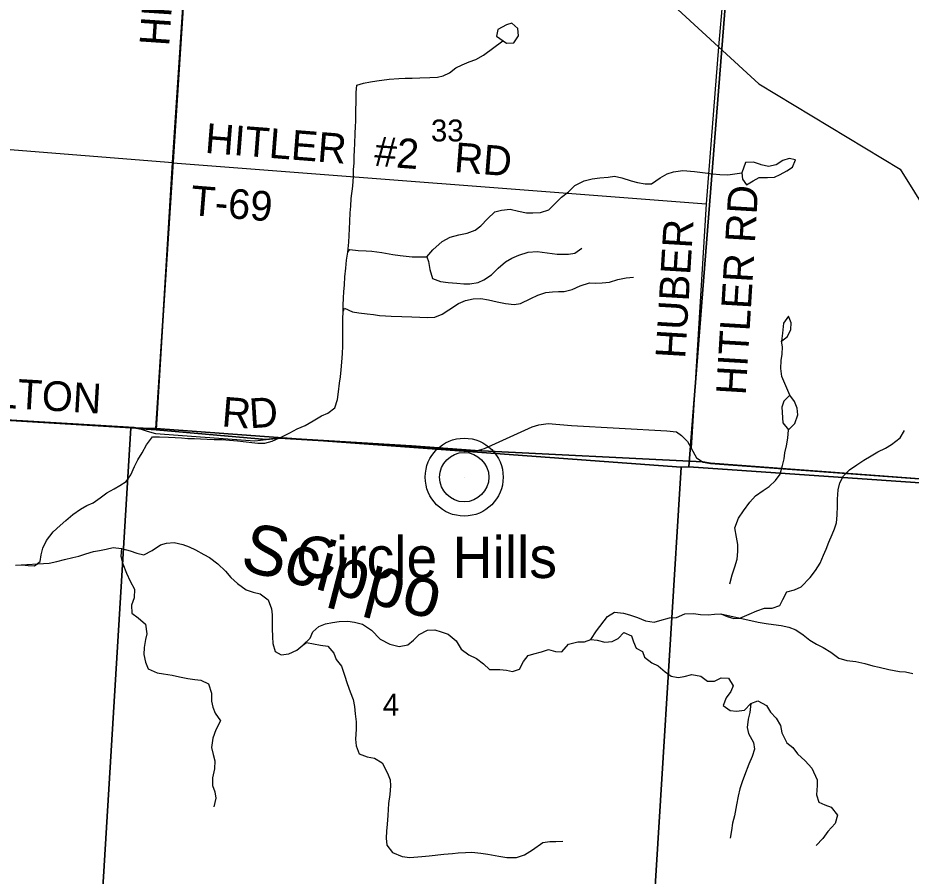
# Model space of a CAD drawing. Extents: x 0 to 42.5, y 0 to 22.
# Drawn here: x 3.26 to 4.113, y 18.558 to 19.377 of the extents above; entities that cross this region are included whole.
import ezdxf

# ---------------------------------------------------------------- set-up
doc = ezdxf.new("R2010")
doc.units = 0
for name, color, linetype in [('GM_X_County_Road', 7, 'Continuous'), ('GM_X_County_Road_Text', 7, 'Continuous'), ('GM_X_Interchange_Ramps', 7, 'Continuous'), ('GM_X_Minor_Lake', 7, 'Continuous'), ('GM_X_Minor_River', 7, 'Continuous'), ('GM_X_Minor_River_Text', 7, 'Continuous'), ('GM_X_Section', 7, 'Continuous'), ('GM_X_Section_Text', 7, 'Continuous'), ('GM_X_State_Route', 7, 'Continuous'), ('GM_X_Township_Road', 7, 'Continuous'), ('GM_X_Township_Road_Text', 7, 'Continuous'), ('GM_X_Unincorporated', 7, 'Continuous'), ('GM_X_Unincorporated_Location', 7, 'Continuous'), ('GM_X_Unincorporated_Text', 7, 'Continuous')]:
    doc.layers.add(name, color=color, linetype=linetype)

msp = doc.modelspace()

# ---------------------------------------------------------------- linework, layer by layer
at = {"layer": 'GM_X_County_Road'}
for points in [[(3.12006, 19.00078), (3.37089, 18.98588), (3.37753, 18.98441), (3.38325, 18.98268)], [(3.70116, 18.96488), (3.70559, 18.96598), (3.75099, 18.98664), (3.75747, 18.98856), (3.76636, 18.98976), (3.78846, 18.98784), (3.87969, 18.98299), (3.88872, 18.98184), (3.89365, 18.97856), (3.8994, 18.9728), (3.90285, 18.96641)], [(3.38325, 18.98268), (3.39135, 18.98024), (3.48609, 18.97319), (3.49698, 18.97445), (3.50982, 18.97594), (3.63593, 18.96814), (3.69673, 18.96377), (3.70116, 18.96488)], [(3.90285, 18.96641), (3.90811, 18.9572), (3.91419, 18.95293), (3.92142, 18.95178), (4.14686, 18.93496)]]:
    msp.add_lwpolyline(points, dxfattribs=at)
at = {"layer": 'GM_X_Interchange_Ramps'}
for points in [[(3.11995, 19.00104), (3.37078, 18.98615), (3.37742, 18.98467), (3.39197, 18.98393), (3.40756, 19.23914), (3.43715, 19.68433), (3.46832, 20.23391), (3.46843, 20.23651), (3.47315, 20.34124), (3.47328, 20.34399), (3.48511, 20.52333), (3.49253, 20.65067), (3.50401, 20.9), (2.3057, 20.9)], [(3.43715, 19.68433), (3.40756, 19.23914), (3.39197, 18.98393), (3.49687, 18.97472), (3.50971, 18.97621), (3.63582, 18.96841), (3.69662, 18.96404), (3.91408, 18.95319), (3.92131, 18.95204), (4.14675, 18.93523), (4.15813, 18.93579), (4.3409, 18.92195), (4.67232, 18.89662), (4.75971, 18.88954), (4.92631, 18.87711), (5.43521, 18.83912), (5.4438, 18.83893), (5.45275, 18.95149)], [(5.32269, 17.21064), (5.36305, 17.75335), (5.38697, 18.0749), (5.4438, 18.83893), (5.43521, 18.83912), (4.92631, 18.87711), (4.75971, 18.88954), (4.67232, 18.89662), (4.3409, 18.92195), (4.15813, 18.93579), (4.14675, 18.93523), (3.92131, 18.95204), (3.91408, 18.95319), (3.69662, 18.96404), (3.63582, 18.96841), (3.50971, 18.97621), (3.49687, 18.97472), (3.39197, 18.98393), (3.37742, 18.98467), (3.37078, 18.98615), (3.11995, 19.00104)]]:
    msp.add_lwpolyline(points, dxfattribs=at)
at = {"layer": 'GM_X_Minor_Lake'}
for points in [[(3.71708, 19.35974), (3.72633, 19.35303), (3.73334, 19.35336), (3.73793, 19.35999), (3.7374, 19.36702), (3.73156, 19.37219), (3.72643, 19.37054)], [(3.72643, 19.37054), (3.71826, 19.366), (3.71708, 19.35974)], [(3.95117, 19.22919), (3.95178, 19.2233), (3.95572, 19.21776), (3.96219, 19.22171), (3.9677, 19.22472), (3.97566, 19.22485), (3.9823, 19.225), (3.98781, 19.22763), (3.99408, 19.2312), (3.99979, 19.23477), (4.00267, 19.2416), (3.99643, 19.24297), (3.99035, 19.24092), (3.98407, 19.23677), (3.97667, 19.2353), (3.96967, 19.23687), (3.96901, 19.23712)], [(3.96901, 19.23712), (3.96249, 19.23957), (3.95472, 19.23905), (3.95117, 19.22919)]]:
    msp.add_lwpolyline(points, dxfattribs=at)
at = {"layer": 'GM_X_Minor_River'}
for points in [[(3.38256, 18.96942), (3.38829, 18.97699), (3.39511, 18.97713), (3.40363, 18.97689), (3.40989, 18.97666), (3.41614, 18.97605), (3.42201, 18.97563), (3.42845, 18.9754), (3.43413, 18.97517), (3.44057, 18.97494), (3.44739, 18.97471), (3.45497, 18.97447), (3.46198, 18.97385), (3.46955, 18.97324), (3.47769, 18.97223), (3.48338, 18.97163), (3.48906, 18.97121), (3.49569, 18.97098), (3.50252, 18.97302), (3.5124, 18.97733), (3.51943, 18.9809), (3.52666, 18.98484), (3.53407, 18.98803), (3.54167, 18.99235), (3.54985, 18.99724), (3.55574, 18.99986), (3.56259, 19.00495), (3.56491, 19.01292), (3.56609, 19.02013), (3.56709, 19.0283), (3.56789, 19.03456), (3.56868, 19.04121), (3.5693, 19.04843), (3.56991, 19.05679), (3.57015, 19.06382), (3.57019, 19.07028), (3.57004, 19.07674), (3.57011, 19.08967), (3.57054, 19.09689), (3.57057, 19.10259), (3.5708, 19.10981), (3.57103, 19.11551), (3.57164, 19.12216), (3.57206, 19.12995), (3.57287, 19.13811), (3.57367, 19.14571), (3.57486, 19.1535), (3.57586, 19.16318), (3.57651, 19.17572), (3.57674, 19.18275), (3.57717, 19.19111), (3.57778, 19.19738), (3.5782, 19.2046), (3.5796, 19.21656), (3.58022, 19.22568), (3.58045, 19.23214), (3.58087, 19.23879), (3.58109, 19.24468), (3.58132, 19.25114), (3.58155, 19.25703), (3.58199, 19.2671), (3.58221, 19.27318), (3.58244, 19.27907), (3.5825, 19.28895), (3.58274, 19.29751), (3.58298, 19.30587), (3.5834, 19.31308), (3.58986, 19.31475), (3.59669, 19.31623), (3.60275, 19.31714), (3.61432, 19.31859), (3.6238, 19.31929), (3.62968, 19.31963), (3.6365, 19.31978), (3.6437, 19.32011), (3.65318, 19.32024), (3.66057, 19.32076), (3.66607, 19.32187), (3.67215, 19.32468), (3.67824, 19.32958), (3.68414, 19.33239), (3.69078, 19.3352), (3.69724, 19.33744), (3.70446, 19.34158), (3.72302, 19.35521)], [(3.57486, 19.1535), (3.57677, 19.15595), (3.58472, 19.15495), (3.5923, 19.15471), (3.59798, 19.1543), (3.60726, 19.15329), (3.61805, 19.15132), (3.62486, 19.15032), (3.63073, 19.14972), (3.63641, 19.14911), (3.65043, 19.14902), (3.65597, 19.15583), (3.66511, 19.16356), (3.67272, 19.16769), (3.68088, 19.17011), (3.68885, 19.17158), (3.69644, 19.17457), (3.70196, 19.17853), (3.70826, 19.18533), (3.71531, 19.19193), (3.72176, 19.1936), (3.7301, 19.19469), (3.73786, 19.19255), (3.74543, 19.19098), (3.75149, 19.19094), (3.75907, 19.19146), (3.76686, 19.19408), (3.77277, 19.19955), (3.77906, 19.20616), (3.78572, 19.21125), (3.79182, 19.2171), (3.80056, 19.22161), (3.80816, 19.22365), (3.81555, 19.22436), (3.8237, 19.22526), (3.82958, 19.22617), (3.83658, 19.22442), (3.84547, 19.22151), (3.85152, 19.21995), (3.85891, 19.21876), (3.86497, 19.21891), (3.87315, 19.22456), (3.88, 19.22832), (3.88607, 19.23018), (3.8948, 19.23146), (3.90616, 19.23043), (3.91619, 19.22942), (3.92358, 19.22842), (3.9302, 19.22762), (3.93797, 19.22738), (3.95117, 19.22919)], [(3.65043, 19.14902), (3.65192, 19.14445), (3.65339, 19.13703), (3.6558, 19.12827), (3.66356, 19.12556), (3.67075, 19.12456), (3.67908, 19.12375), (3.68571, 19.12313), (3.6914, 19.1231), (3.69936, 19.12457), (3.70487, 19.12719), (3.71229, 19.1319), (3.71839, 19.13813), (3.72563, 19.14436), (3.73152, 19.14774), (3.73817, 19.15055), (3.7471, 19.15353), (3.75582, 19.15423), (3.76547, 19.15284), (3.77475, 19.15145), (3.78555, 19.15157), (3.79181, 19.15248), (3.79828, 19.15738)], [(3.57054, 19.09689), (3.57169, 19.09992), (3.57944, 19.09645), (3.58531, 19.09546), (3.59326, 19.09446), (3.59951, 19.09385), (3.60519, 19.09305), (3.61087, 19.09283), (3.61636, 19.09241), (3.62659, 19.09215), (3.63607, 19.09171), (3.64364, 19.09128), (3.65084, 19.09124), (3.65804, 19.09138), (3.66488, 19.09419), (3.67135, 19.09833), (3.68067, 19.10435), (3.68732, 19.10735), (3.69453, 19.10901), (3.70211, 19.10916), (3.7093, 19.10797), (3.71763, 19.10621), (3.72558, 19.10444), (3.73391, 19.10344), (3.73998, 19.10454), (3.74986, 19.10923), (3.75632, 19.11242), (3.76411, 19.11484), (3.77055, 19.11575), (3.77605, 19.1159), (3.78155, 19.11606), (3.78913, 19.11772), (3.79693, 19.12128), (3.80566, 19.12408), (3.81153, 19.12404), (3.81779, 19.12419), (3.8248, 19.1249), (3.83277, 19.12751), (3.84074, 19.12898), (3.84776, 19.12951)], [(3.98924, 19.06862), (3.99483, 19.07288), (3.9979, 19.0797), (3.99832, 19.08616), (3.99571, 19.09245), (3.99112, 19.08582), (3.98999, 19.07616)], [(3.98999, 19.07616), (3.98924, 19.06862)], [(3.99714, 19.0168), (3.98944, 19.03468), (3.98835, 19.04229), (3.98897, 19.05008), (3.98976, 19.05597), (3.99018, 19.06319), (3.98924, 19.06862)], [(3.99581, 18.98396), (3.99581, 18.98392), (4.00172, 18.98997), (4.0048, 18.99812), (4.00408, 19.0044), (4.00166, 19.01087), (3.99714, 19.0168), (3.99123, 19.01113), (3.98952, 19.00535)], [(3.98952, 19.00535), (3.99035, 18.99042), (3.99581, 18.98396)], [(3.93978, 18.8368), (3.94211, 18.84533), (3.94443, 18.85311), (3.94675, 18.86032), (3.94736, 18.86773), (3.9474, 18.87419), (3.94611, 18.88142), (3.94465, 18.89017), (3.94812, 18.89946), (3.95271, 18.90646), (3.95901, 18.9146), (3.96416, 18.92065), (3.97158, 18.92592), (3.97748, 18.92968), (3.98339, 18.93535), (3.98778, 18.94159), (3.99011, 18.94975), (3.99166, 18.95601), (3.99245, 18.9619), (3.99382, 18.96854), (3.99519, 18.97594), (3.99596, 18.98382)], [(3.93127, 18.80815), (3.93713, 18.80564), (3.94356, 18.8037), (3.94925, 18.80404), (3.95836, 18.80779), (3.96558, 18.81097), (3.97299, 18.81359), (3.98038, 18.81354), (3.98741, 18.81596), (3.99047, 18.82184), (3.99431, 18.82922), (4.00171, 18.83089), (4.00779, 18.83389), (4.01637, 18.84277), (4.02171, 18.84939), (4.02592, 18.85639), (4.02938, 18.86416), (4.03169, 18.86985), (4.03438, 18.87667), (4.03746, 18.88387), (4.03977, 18.88937), (4.04169, 18.89506), (4.04231, 18.90228), (4.04255, 18.91121), (4.04278, 18.91767), (4.0434, 18.92641), (4.04477, 18.93324), (4.04841, 18.93987), (4.05413, 18.94554), (4.06117, 18.95043), (4.06782, 18.95495), (4.07486, 18.95909), (4.08113, 18.96266), (4.08836, 18.96641), (4.09425, 18.9698), (4.10263, 18.97621), (4.10665, 18.98321)], [(3.25756, 18.85448), (3.26401, 18.85482), (3.26969, 18.85421), (3.27556, 18.85398), (3.28108, 18.85794), (3.28207, 18.86439), (3.28362, 18.87084), (3.28707, 18.87805), (3.29357, 18.88656), (3.30005, 18.8926), (3.30557, 18.89712), (3.31243, 18.90297), (3.31966, 18.90806), (3.32574, 18.91144), (3.33163, 18.91425), (3.33848, 18.91896), (3.34476, 18.92367), (3.35161, 18.92762), (3.35731, 18.93062), (3.36321, 18.93458), (3.3676, 18.94082), (3.37125, 18.94878), (3.37451, 18.95522), (3.37834, 18.96185), (3.38256, 18.96942)], [(3.25756, 18.85448), (3.28979, 18.85655), (3.297, 18.85802), (3.30421, 18.85988), (3.31218, 18.86192), (3.31787, 18.86321), (3.3247, 18.86526), (3.33211, 18.86749), (3.3378, 18.8686), (3.34406, 18.86989), (3.35089, 18.87155), (3.35884, 18.87055), (3.36698, 18.86841), (3.37341, 18.86609), (3.38022, 18.86433), (3.38801, 18.86846), (3.396, 18.87393), (3.40189, 18.8756), (3.40909, 18.87631), (3.41723, 18.87436), (3.42328, 18.87223), (3.42932, 18.86934), (3.43726, 18.86473), (3.44292, 18.86184), (3.45066, 18.8559), (3.45819, 18.84882), (3.46327, 18.8427), (3.46949, 18.83696), (3.47779, 18.83102), (3.48441, 18.82869), (3.49122, 18.82713), (3.49896, 18.82157), (3.50213, 18.813), (3.50266, 18.8071), (3.50262, 18.80121), (3.50277, 18.79399), (3.50291, 18.786), (3.50344, 18.77992), (3.50548, 18.77211), (3.51133, 18.76884), (3.51854, 18.76994), (3.52614, 18.7735), (3.53185, 18.77802), (3.53891, 18.78501), (3.54159, 18.79089), (3.54731, 18.79598), (3.55358, 18.79841), (3.56041, 18.7997), (3.56667, 18.8008), (3.575, 18.80112), (3.58144, 18.80013), (3.58882, 18.79838), (3.5975, 18.79243), (3.60579, 18.78401), (3.61504, 18.7792), (3.62394, 18.77705), (3.63228, 18.77852), (3.6378, 18.78286), (3.64314, 18.78852), (3.65093, 18.79246), (3.65814, 18.7928), (3.66419, 18.79105), (3.67081, 18.78854), (3.67835, 18.78222), (3.68323, 18.77439), (3.69058, 18.76883), (3.69795, 18.76555), (3.70436, 18.76019), (3.7104, 18.75502), (3.72006, 18.75496), (3.7265, 18.75416), (3.73236, 18.75298), (3.73901, 18.75541), (3.74265, 18.76242), (3.74724, 18.76828), (3.75274, 18.76976), (3.75995, 18.77181), (3.7666, 18.77405), (3.77322, 18.7721), (3.77947, 18.77168), (3.78576, 18.77906), (3.79468, 18.78128), (3.80113, 18.78143), (3.80702, 18.78367), (3.81256, 18.79181), (3.82287, 18.80543), (3.82953, 18.80976), (3.83824, 18.80875), (3.84392, 18.80719), (3.85148, 18.80448), (3.85923, 18.80139), (3.86756, 18.80001), (3.87306, 18.80187), (3.88217, 18.80428), (3.889, 18.80462), (3.89679, 18.80818), (3.90494, 18.80851), (3.91175, 18.80752), (3.91914, 18.80709), (3.92502, 18.80781), (3.93127, 18.80815)], [(3.35884, 18.87055), (3.35804, 18.86315), (3.36008, 18.85572), (3.36344, 18.84696), (3.36699, 18.83933), (3.3713, 18.83151), (3.37088, 18.82353), (3.36818, 18.81633), (3.36851, 18.80872), (3.37455, 18.80431), (3.38171, 18.79818), (3.3828, 18.78905), (3.38182, 18.78355), (3.38025, 18.77596), (3.38021, 18.76911), (3.38169, 18.76207), (3.38411, 18.75559), (3.3928, 18.75174), (3.39886, 18.75094), (3.40719, 18.74955), (3.414, 18.74799), (3.42214, 18.74642), (3.42877, 18.74542), (3.43445, 18.74482), (3.44201, 18.74135), (3.44479, 18.7324), (3.44475, 18.72461), (3.44585, 18.71909), (3.44809, 18.71318), (3.45316, 18.70592), (3.44894, 18.6974), (3.44586, 18.68944), (3.44467, 18.68051), (3.44615, 18.67366), (3.44801, 18.66776), (3.44758, 18.66016), (3.44582, 18.65143), (3.44578, 18.6442), (3.44802, 18.63811), (3.44893, 18.63202), (3.44679, 18.62367)], [(3.93127, 18.80815), (3.96685, 18.80013), (3.97442, 18.79894), (3.98142, 18.79776), (3.98881, 18.79695), (3.99619, 18.79538), (4.0028, 18.79287), (4.00979, 18.78807), (4.0162, 18.7829), (4.02243, 18.77925), (4.02904, 18.77597), (4.0364, 18.77155), (4.04395, 18.76581), (4.05151, 18.76367), (4.06022, 18.76247), (4.06874, 18.76051), (4.07649, 18.75856), (4.08236, 18.7572), (4.09163, 18.75486), (4.10185, 18.75308), (4.10753, 18.75266), (4.11453, 18.7511)], [(3.80702, 18.78367), (3.81307, 18.78306), (3.82045, 18.78092), (3.82728, 18.78164), (3.83298, 18.78445), (3.83851, 18.79031), (3.84588, 18.78722), (3.84774, 18.78132), (3.85017, 18.77522), (3.8564, 18.77214), (3.85826, 18.76662), (3.86543, 18.76125), (3.87129, 18.75855), (3.87788, 18.75262), (3.88373, 18.74859), (3.89036, 18.7474), (3.89623, 18.74813), (3.90345, 18.75017), (3.91196, 18.7486), (3.91857, 18.7438), (3.9252, 18.74395), (3.93147, 18.74695), (3.93867, 18.74652), (3.94298, 18.73946), (3.94087, 18.73397), (3.93628, 18.72772), (3.9334, 18.72052), (3.94, 18.71592), (3.94606, 18.71512), (3.95383, 18.71621), (3.95993, 18.72244), (3.96639, 18.72487), (3.97489, 18.72044), (3.97864, 18.71434), (3.98411, 18.7086), (3.98804, 18.70154), (3.98932, 18.69431), (3.99438, 18.68478), (4.00004, 18.68056), (4.00436, 18.67445), (4.0119, 18.66775), (4.01811, 18.66068), (4.02335, 18.64962), (4.02332, 18.64411), (4.02269, 18.63518), (4.02474, 18.62832), (4.0306, 18.62563), (4.03664, 18.62331), (4.04266, 18.61567), (4.04034, 18.60789), (4.03328, 18.60033), (4.02851, 18.59352), (4.0224, 18.58672)], [(3.53185, 18.77802), (3.53547, 18.78066), (3.54228, 18.77948), (3.54891, 18.77829), (3.55572, 18.7773), (3.56156, 18.77042), (3.56379, 18.76451), (3.56887, 18.75802), (3.57166, 18.74964), (3.57427, 18.74145), (3.57706, 18.73345), (3.58005, 18.72621), (3.58133, 18.71955), (3.58205, 18.7127), (3.58295, 18.70509), (3.58291, 18.69787), (3.58228, 18.68837), (3.58281, 18.6821), (3.5858, 18.67448), (3.59336, 18.67139), (3.60036, 18.6702), (3.60773, 18.66578), (3.61278, 18.65587), (3.61521, 18.64958), (3.61574, 18.64368), (3.61493, 18.63552), (3.61375, 18.62697), (3.61333, 18.62108), (3.61311, 18.61538), (3.61249, 18.60721), (3.61188, 18.60056), (3.61146, 18.59373), (3.61218, 18.58726), (3.61744, 18.58019), (3.6267, 18.57633), (3.63428, 18.57552), (3.64546, 18.5764), (3.65267, 18.57693), (3.66651, 18.57855), (3.67485, 18.57925), (3.68035, 18.57979), (3.68736, 18.58031), (3.69343, 18.58047), (3.70195, 18.57965), (3.70857, 18.57866), (3.71917, 18.57669), (3.72693, 18.5755), (3.73603, 18.57525), (3.74362, 18.57786), (3.75123, 18.58275), (3.76113, 18.58972), (3.76795, 18.59063), (3.77345, 18.59078), (3.78027, 18.59112)], [(3.95993, 18.72244), (3.95894, 18.71389), (3.95738, 18.70763), (3.9562, 18.69966), (3.95768, 18.69376), (3.96255, 18.68517), (3.96346, 18.67889), (3.96115, 18.67188), (3.95788, 18.66467), (3.95384, 18.65368), (3.95153, 18.64761), (3.94921, 18.64097), (3.94765, 18.63395), (3.94628, 18.62579), (3.94432, 18.61516), (3.94238, 18.60833), (3.94139, 18.60111), (3.94021, 18.5939)]]:
    msp.add_lwpolyline(points, dxfattribs=at)
at = {"layer": 'GM_X_Section'}
for points in [[(2.90759, 19.50738), (3.42438, 19.48993), (3.39164, 18.98496), (3.36778, 18.98583), (2.87643, 19.01565)], [(3.42438, 19.48993), (3.94032, 19.4526), (3.90077, 18.94861), (3.89319, 18.94826), (3.39164, 18.98496)], [(3.94032, 19.4526), (4.45285, 19.41472), (4.41842, 18.91278), (4.41142, 18.91319), (3.90077, 18.94861)], [(2.87643, 19.01565), (3.36778, 18.98583), (3.33838, 18.5047), (2.81447, 18.53809), (2.83799, 19.01773)], [(3.36778, 18.98583), (3.39164, 18.98496), (3.89319, 18.94826), (3.86362, 18.47054), (3.33838, 18.5047)], [(3.90077, 18.94861), (4.41142, 18.91319), (4.37823, 18.43283), (3.86362, 18.47054), (3.89319, 18.94826)]]:
    msp.add_lwpolyline(points, close=True, dxfattribs=at)
at = {"layer": 'GM_X_State_Route'}
for points in [[(3.5071, 19.65897), (3.59905, 19.63357), (3.64438, 19.6067), (3.67123, 19.58594), (3.73828, 19.52485), (3.92891, 19.34957)], [(3.92891, 19.34957), (3.96734, 19.31432), (4.10255, 19.23265), (4.17083, 19.12302), (4.20016, 19.07649), (4.3, 18.96785), (4.34101, 18.92169)]]:
    msp.add_lwpolyline(points, dxfattribs=at)
at = {"layer": 'GM_X_Township_Road'}
for p, q in [((3.95904, 19.70046), (3.92891, 19.34957)), ((3.43726, 19.68407), (3.40767, 19.23888)), ((3.92891, 19.34957), (3.91718, 19.19966)), ((3.40767, 19.23888), (3.15004, 19.25958)), ((3.40767, 19.23888), (3.91718, 19.19966)), ((3.91718, 19.19966), (3.90285, 18.96641))]:
    msp.add_line(p, q, dxfattribs=at)
at = {"layer": 'GM_X_Unincorporated'}
for radius in [0.0372, 0.02358]:
    msp.add_circle((3.68607, 18.93863), radius, dxfattribs=at)
at = {"layer": 'GM_X_Unincorporated_Location'}
msp.add_line((3.68607, 18.93863), (3.68607, 18.93863), dxfattribs=at)

# ---------------------------------------------------------------- texts
at = {"layer": 'GM_X_County_Road_Text'}
for s, height, rotation, p in [('TARLTON', 0.028409, 356.61645, (3.16186, 19.00974)), ('R', 0.02841, 355.40523, (3.45389, 18.9872)), ('D', 0.02841, 3.62292, (3.48152, 18.9853))]:
    msp.add_text(s, height=height, rotation=rotation, dxfattribs=at).set_placement(p)
at = {"layer": 'GM_X_Minor_River_Text'}
msp.add_text('Scippo', height=0.047349, rotation=345.53079, dxfattribs=at).set_placement((3.47062, 18.85072))
at = {"layer": 'GM_X_Section_Text'}
for s, height, p in [('33', 0.020928, (3.65433, 19.25924)), ('4', 0.02093, (3.60828, 18.71085))]:
    msp.add_text(s, height=height, rotation=0.00001, dxfattribs=at).set_placement(p)
at = {"layer": 'GM_X_Township_Road_Text'}
for s, rotation, p in [('HITLER', 86.12135, (3.40426, 19.34975)), ('HITLER', 355.54209, (3.4379, 19.24843)), ('#2', 355.69548, (3.59954, 19.23594)), ('RD', 355.56225, (3.67581, 19.2301)), ('T-69', 355.41182, (3.42392, 19.18901)), ('HITLER RD', 86.55566, (3.95495, 19.01648)), ('HUBER', 86.55053, (3.89712, 19.05133))]:
    msp.add_text(s, height=0.028409, rotation=rotation, dxfattribs=at).set_placement(p)
at = {"layer": 'GM_X_Unincorporated_Text'}
msp.add_text('Circle Hills', height=0.0394886, rotation=0.00001, dxfattribs=at).set_placement((3.52537, 18.84231))

doc.saveas('drawing.dxf')
